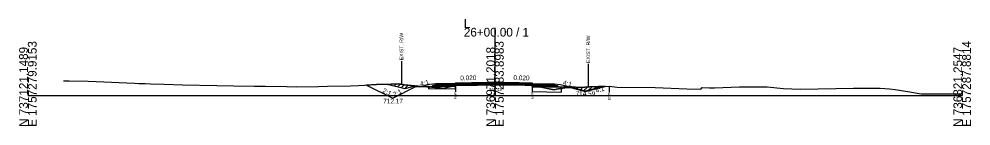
# Model space of a CAD drawing. Extents: x -26 to 4303, y -10 to 9577.
# Drawn here: x 997.2 to 1302.8, y 5990.3 to 6024.5 of the extents above; entities that cross this region are included whole.
import ezdxf

# ---------------------------------------------------------------- set-up
doc = ezdxf.new("R2010")
doc.units = 0
for name, color, linetype in [('Exist CMT Pavement', 7, 'Continuous'), ('Old_Level_10', 7, 'Continuous'), ('Old_Level_2', 7, 'Continuous'), ('Pattern 1', 7, 'Continuous'), ('Prop CMT Conc Surface', 7, 'Continuous'), ('Prop CMT Concrete Structures', 7, 'Continuous'), ('Prop CMT Concrete Wall', 7, 'Continuous'), ('Prop CMT Pvmt Course 1', 7, 'Continuous'), ('Prop CMT Pvmt Course 1 CG', 7, 'Continuous'), ('Prop CMT Pvmt Course 1 Wedge', 7, 'Continuous'), ('Prop CMT Pvmt Course 2', 7, 'Continuous'), ('Prop CMT Pvmt Course 2 Wedge', 7, 'Continuous'), ('Prop CMT Pvmt Course 3', 7, 'Continuous'), ('Prop CMT Pvmt Surface', 7, 'Continuous'), ('Prop CMT Pvmt Surface Shoulder', 7, 'Continuous'), ('Prop CMT Pvmt Wedge Surface 1', 7, 'Continuous'), ('Prop CMT Pvmt Wedge Surface 2', 7, 'Continuous'), ('Prop CMT Pvmt Wedge Surface 3', 7, 'Continuous'), ('Prop CMT Shld Paved Course 1', 7, 'Continuous'), ('Prop CMT Shld Paved Course 2', 7, 'Continuous'), ('Prop CMT Shld Paved Course 3', 7, 'Continuous'), ('Prop CMT Slope Grass', 7, 'Continuous'), ('Prop CMT Subgrade Earthwork', 7, 'Continuous'), ('Prop Road Sect_ Recs - UC Shallow (Outline)', 7, 'Continuous'), ('Prop Shade Light', 7, 'Continuous'), ('Prop XS DDE Elevations', 7, 'Continuous'), ('Prop XS Ditch Standard Text', 7, 'Continuous'), ('Prop XS Earthwork Shape', 7, 'Continuous'), ('Prop XS Hydro Elevations', 7, 'Continuous'), ('Prop XS SE Text', 7, 'Continuous'), ('Prop XS Side Slope Text', 7, 'Continuous'), ('Prop XS Wedging', 7, 'Continuous')]:
    doc.layers.add(name, color=color, linetype=linetype)

msp = doc.modelspace()

# ---------------------------------------------------------------- linework, layer by layer
at = {"layer": 'Exist CMT Pavement'}
for points in [[(1150, 6004.13), (1133, 6003.79)], [(1150, 6004.13), (1167, 6003.79)]]:
    msp.add_lwpolyline(points, dxfattribs=at)
at = {"layer": 'Old_Level_10'}
for p, q in [((1108.71, 6003.38), (1117.14, 5999.17)), ((1117.14, 5999.17), (1124.55, 6002.88)), ((1124.55, 6002.88), (1126.55, 6002.98))]:
    msp.add_line(p, q, dxfattribs=at)
at = {"layer": 'Old_Level_2'}
for p, q in [((1150, 6000), (1150, 6021.72)), ((1150, 6000), (1150, 6021.72)), ((1000, 6000), (1150, 6000)), ((1000, 6000), (1150, 6000)), ((1150, 6000), (1300, 6000)), ((1150, 6000), (1300, 6000))]:
    msp.add_line(p, q, dxfattribs=at)
at = {"layer": 'Pattern 1'}
for p, q in [((1116.46, 6003.35), (1116.74, 6003.63)), ((1117.59, 6003.07), (1118.22, 6003.7)), ((1118.72, 6002.79), (1119.61, 6003.68)), ((1119.85, 6002.51), (1120.85, 6003.5)), ((1120.98, 6002.22), (1122.14, 6003.38)), ((1122.86, 6002.68), (1123.44, 6003.26)), ((1161.92, 6003.05), (1162.18, 6003.32)), ((1163.06, 6002.78), (1163.34, 6003.06)), ((1164.45, 6002.75), (1164.5, 6002.81)), ((1173.84, 6002.57), (1174.01, 6002.74)), ((1175.05, 6002.37), (1175.44, 6002.75)), ((1176.18, 6002.08), (1176.75, 6002.66)), ((1177.31, 6001.8), (1178.18, 6002.67)), ((1178.44, 6001.52), (1179.68, 6002.76)), ((1179.96, 6001.62), (1181.17, 6002.83)), ((1181.84, 6002.09), (1182.63, 6002.88)), ((1183.73, 6002.56), (1184.1, 6002.93))]:
    msp.add_line(p, q, dxfattribs=at)
for points in [[(1124.71, 6003.15), (1121, 6002.22), (1115.39, 6003.62), (1116.62, 6003.63), (1119.13, 6003.75), (1120.8, 6003.51), (1124.62, 6003.15)], [(1161.92, 6002.8), (1164.77, 6002.75), (1161.92, 6003.38)], [(1179, 6001.38), (1185.38, 6002.97), (1183.25, 6002.9), (1180.75, 6002.81), (1179.73, 6002.76), (1177.26, 6002.62), (1174.51, 6002.82), (1173.64, 6002.69), (1172.95, 6002.58), (1174.28, 6002.56)]]:
    msp.add_lwpolyline(points, close=True, dxfattribs=at)
at = {"layer": 'Prop CMT Conc Surface'}
for points in [[(1137.34, 6003.63), (1133, 6003.54)], [(1137.34, 6003.42), (1137.34, 6003.63)], [(1161.92, 6003.43), (1161.92, 6003.64)], [(1161.92, 6003.64), (1167, 6003.54)], [(1133, 6003.54), (1133, 6003.33)], [(1133, 6003.33), (1137.34, 6003.42)], [(1167, 6003.33), (1161.92, 6003.43)], [(1167, 6003.54), (1167, 6003.33)]]:
    msp.add_lwpolyline(points, dxfattribs=at)
at = {"layer": 'Prop CMT Concrete Structures'}
for points in [[(1133, 6003.54), (1133, 6003.79)], [(1137.34, 6003.63), (1133, 6003.54)], [(1150, 6004), (1137.34, 6003.75)], [(1137.34, 6003.75), (1137.34, 6003.63)], [(1150, 6004), (1161.92, 6003.77)], [(1161.92, 6003.77), (1161.92, 6003.64)], [(1161.92, 6003.64), (1167, 6003.54)], [(1167, 6003.54), (1167, 6003.79)]]:
    msp.add_lwpolyline(points, dxfattribs=at)
at = {"layer": 'Prop CMT Pvmt Course 1'}
for points in [[(1137.34, 6003.42), (1133, 6003.33)], [(1133, 6003.33), (1133, 6003)], [(1133, 6003), (1137.34, 6003.08)], [(1137.34, 6003.08), (1137.34, 6003.42)], [(1161.92, 6003.43), (1167, 6003.33)], [(1161.92, 6003.1), (1161.92, 6003.43)], [(1167, 6003), (1161.92, 6003.1)], [(1167, 6003.33), (1167, 6003)]]:
    msp.add_lwpolyline(points, dxfattribs=at)
at = {"layer": 'Prop CMT Pvmt Course 1 Wedge'}
for points in [[(1137.34, 6004.07), (1137.75, 6004.08), (1137.83, 6004.08), (1138.14, 6004.09), (1139.33, 6004.11), (1139.59, 6004.11), (1139.95, 6004.12), (1140.06, 6004.12), (1142.45, 6004.17), (1142.5, 6004.17), (1144.41, 6004.21), (1144.94, 6004.22), (1144.95, 6004.22), (1147.37, 6004.27), (1147.45, 6004.27), (1147.48, 6004.27), (1148.16, 6004.29), (1148.53, 6004.29), (1149.98, 6004.32), (1150, 6004.32)], [(1137.34, 6003.25), (1137.34, 6004.07)], [(1150, 6004.32), (1150, 6003.49)], [(1150, 6004.32), (1151.04, 6004.3), (1151.29, 6004.3), (1151.68, 6004.29), (1152.37, 6004.28), (1152.45, 6004.27), (1154.68, 6004.23), (1154.95, 6004.22), (1157.12, 6004.18), (1157.45, 6004.17), (1157.81, 6004.17), (1159.96, 6004.12), (1160.88, 6004.11), (1161.13, 6004.1), (1161.23, 6004.1), (1161.44, 6004.09), (1161.46, 6004.09), (1161.92, 6004.08)], [(1161.92, 6004.08), (1161.92, 6003.38)], [(1150, 6003.49), (1149.98, 6003.49), (1148.53, 6003.47), (1148.16, 6003.44), (1147.48, 6003.46), (1147.45, 6003.46), (1147.37, 6003.46), (1144.95, 6003.42), (1144.94, 6003.42), (1144.41, 6003.41), (1142.5, 6003.39), (1142.45, 6003.39), (1140.06, 6003.38), (1139.95, 6003.38), (1139.59, 6003.36), (1139.33, 6003.37), (1138.14, 6003.34), (1137.83, 6003.34), (1137.75, 6003.34), (1137.34, 6003.25)], [(1161.92, 6003.38), (1161.46, 6003.4), (1161.44, 6003.4), (1161.23, 6003.4), (1161.13, 6003.4), (1160.88, 6003.41), (1159.96, 6003.41), (1157.81, 6003.43), (1157.45, 6003.43), (1157.12, 6003.44), (1154.95, 6003.47), (1154.68, 6003.47), (1152.45, 6003.46), (1152.37, 6003.46), (1151.68, 6003.47), (1151.29, 6003.48), (1151.04, 6003.47), (1150, 6003.49)]]:
    msp.add_lwpolyline(points, dxfattribs=at)
at = {"layer": 'Prop CMT Pvmt Course 2'}
for points in [[(1133, 6003.79), (1131, 6003.75), (1130.74, 6003.49)], [(1133, 6003.54), (1133, 6003.79)], [(1167, 6003.79), (1169, 6003.75), (1169.26, 6003.49)], [(1167, 6003.54), (1167, 6003.79)], [(1130.74, 6003.49), (1133, 6003.54)], [(1169.26, 6003.49), (1167, 6003.54)]]:
    msp.add_lwpolyline(points, dxfattribs=at)
at = {"layer": 'Prop CMT Pvmt Course 2 Wedge'}
for points in [[(1131, 6003.75), (1129, 6003.59), (1126.55, 6002.98)], [(1169, 6003.75), (1171, 6003.59), (1179, 6001.59), (1184.4, 6002.94)]]:
    msp.add_lwpolyline(points, dxfattribs=at)
at = {"layer": 'Prop CMT Pvmt Course 3'}
for points in [[(1133, 6003.54), (1130.74, 6003.49), (1130.53, 6003.28)], [(1130.53, 6003.28), (1133, 6003.33)], [(1133, 6003.33), (1133, 6003.54)], [(1167, 6003.54), (1169.26, 6003.49), (1169.47, 6003.28)], [(1167, 6003.33), (1167, 6003.54)], [(1169.47, 6003.28), (1167, 6003.33)]]:
    msp.add_lwpolyline(points, dxfattribs=at)
at = {"layer": 'Prop CMT Pvmt Surface'}
for points in [[(1150, 6003.88), (1133, 6003.54)], [(1133, 6003.54), (1133, 6003.79)], [(1150, 6003.88), (1167, 6003.54)], [(1167, 6003.54), (1167, 6003.79)]]:
    msp.add_lwpolyline(points, dxfattribs=at)
at = {"layer": 'Prop CMT Pvmt Surface Shoulder'}
for points in [[(1137.34, 6003.25), (1137.75, 6003.34), (1137.83, 6003.34), (1138.14, 6003.34), (1139.33, 6003.37), (1139.59, 6003.36), (1139.95, 6003.38), (1140.06, 6003.38), (1142.45, 6003.39), (1142.5, 6003.39), (1144.41, 6003.41), (1144.94, 6003.42), (1144.95, 6003.42), (1147.37, 6003.46), (1147.45, 6003.46), (1147.48, 6003.46), (1148.16, 6003.44), (1148.53, 6003.47), (1149.98, 6003.49), (1150, 6003.49)], [(1150, 6003.49), (1151.04, 6003.47), (1151.29, 6003.48), (1151.68, 6003.47), (1152.37, 6003.46), (1152.45, 6003.46), (1154.68, 6003.47), (1154.95, 6003.47), (1157.12, 6003.44), (1157.45, 6003.43), (1157.81, 6003.43), (1159.96, 6003.41), (1160.88, 6003.41), (1161.13, 6003.4), (1161.23, 6003.4), (1161.44, 6003.4), (1161.46, 6003.4), (1161.92, 6003.38)]]:
    msp.add_lwpolyline(points, dxfattribs=at)
at = {"layer": 'Prop CMT Pvmt Wedge Surface 1'}
for p, q in [((1126.55, 6002.98), (1129.02, 6002.79)), ((1133.02, 6002.87), (1129.02, 6002.79)), ((1137.34, 6002.96), (1133.02, 6002.87)), ((1161.92, 6002.97), (1166.98, 6002.87)), ((1166.98, 6002.87), (1174.47, 6002.72))]:
    msp.add_line(p, q, dxfattribs=at)
for points in [[(1137.34, 6003.25), (1137.34, 6002.96)], [(1161.92, 6003.38), (1161.92, 6002.97)]]:
    msp.add_lwpolyline(points, dxfattribs=at)
at = {"layer": 'Prop CMT Pvmt Wedge Surface 2'}
for points in [[(1137.34, 6003.75), (1137.75, 6003.76), (1137.83, 6003.76), (1138.14, 6003.77), (1139.33, 6003.79), (1139.59, 6003.8), (1139.95, 6003.8), (1140.06, 6003.8), (1142.45, 6003.85), (1142.5, 6003.85), (1144.41, 6003.89), (1144.94, 6003.9), (1144.95, 6003.9), (1147.37, 6003.95), (1147.45, 6003.95), (1147.48, 6003.95), (1148.16, 6003.97), (1148.53, 6003.97), (1149.98, 6004), (1150, 6004)], [(1150, 6003.88), (1149.98, 6003.88), (1148.53, 6003.85), (1148.16, 6003.84), (1147.48, 6003.83), (1147.45, 6003.83), (1147.37, 6003.83), (1144.95, 6003.78), (1144.94, 6003.78), (1144.41, 6003.77), (1142.5, 6003.73), (1142.45, 6003.73), (1140.06, 6003.68), (1139.95, 6003.68), (1139.59, 6003.67), (1139.33, 6003.67), (1138.14, 6003.64), (1137.83, 6003.63), (1137.75, 6003.63), (1137.34, 6003.63)], [(1137.34, 6002.6), (1137.34, 6003.75)], [(1150, 6004), (1150, 6003.88)], [(1150, 6004), (1151.04, 6003.98), (1151.29, 6003.98), (1151.68, 6003.97), (1152.37, 6003.96), (1152.45, 6003.95), (1154.68, 6003.91), (1154.95, 6003.9), (1157.12, 6003.86), (1157.45, 6003.85), (1157.81, 6003.85), (1159.96, 6003.8), (1160.88, 6003.79), (1161.13, 6003.78), (1161.23, 6003.78), (1161.44, 6003.77), (1161.46, 6003.77), (1161.92, 6003.77)], [(1161.92, 6003.64), (1161.46, 6003.65), (1161.44, 6003.65), (1161.23, 6003.65), (1161.13, 6003.66), (1160.88, 6003.66), (1159.96, 6003.68), (1157.81, 6003.72), (1157.45, 6003.73), (1157.12, 6003.74), (1154.95, 6003.78), (1154.68, 6003.78), (1152.45, 6003.83), (1152.37, 6003.83), (1151.68, 6003.84), (1151.29, 6003.85), (1151.04, 6003.86), (1150, 6003.88)], [(1161.92, 6003.77), (1161.92, 6002.73)]]:
    msp.add_lwpolyline(points, dxfattribs=at)
at = {"layer": 'Prop CMT Pvmt Wedge Surface 3'}
for points in [[(1137.34, 6003.63), (1137.75, 6003.63), (1137.83, 6003.63), (1138.14, 6003.64), (1139.33, 6003.67), (1139.59, 6003.67), (1139.95, 6003.68), (1140.06, 6003.68), (1142.45, 6003.73), (1142.5, 6003.73), (1144.41, 6003.77), (1144.94, 6003.78), (1144.95, 6003.78), (1147.37, 6003.83), (1147.45, 6003.83), (1147.48, 6003.83), (1148.16, 6003.84), (1148.53, 6003.85), (1149.98, 6003.88), (1150, 6003.88)], [(1150, 6003.67), (1149.98, 6003.67), (1148.53, 6003.64), (1148.16, 6003.63), (1147.48, 6003.62), (1147.45, 6003.62), (1147.37, 6003.62), (1144.95, 6003.57), (1144.94, 6003.57), (1144.41, 6003.56), (1142.5, 6003.52), (1142.45, 6003.52), (1140.06, 6003.47), (1139.95, 6003.47), (1139.59, 6003.46), (1139.33, 6003.46), (1138.14, 6003.43), (1137.83, 6003.43), (1137.75, 6003.43), (1137.34, 6003.42)], [(1137.34, 6003.42), (1137.34, 6003.63)], [(1150, 6003.88), (1150, 6003.67)], [(1150, 6003.88), (1151.04, 6003.86), (1151.29, 6003.85), (1151.68, 6003.84), (1152.37, 6003.83), (1152.45, 6003.83), (1154.68, 6003.78), (1154.95, 6003.78), (1157.12, 6003.74), (1157.45, 6003.73), (1157.81, 6003.72), (1159.96, 6003.68), (1160.88, 6003.66), (1161.13, 6003.66), (1161.23, 6003.65), (1161.44, 6003.65), (1161.46, 6003.65), (1161.92, 6003.64)], [(1161.92, 6003.43), (1161.46, 6003.44), (1161.44, 6003.44), (1161.23, 6003.45), (1161.13, 6003.45), (1160.88, 6003.45), (1159.96, 6003.47), (1157.81, 6003.51), (1157.45, 6003.52), (1157.12, 6003.53), (1154.95, 6003.57), (1154.68, 6003.58), (1152.45, 6003.62), (1152.37, 6003.62), (1151.68, 6003.64), (1151.29, 6003.64), (1151.04, 6003.65), (1150, 6003.67)], [(1161.92, 6003.64), (1161.92, 6003.43)]]:
    msp.add_lwpolyline(points, dxfattribs=at)
at = {"layer": 'Prop CMT Shld Paved Course 1'}
for points in [[(1133, 6003.33), (1133, 6003.79)], [(1150, 6003.67), (1133, 6003.33)], [(1150, 6003.67), (1167, 6003.33)], [(1167, 6003.33), (1167, 6003.79)]]:
    msp.add_lwpolyline(points, dxfattribs=at)
at = {"layer": 'Prop CMT Shld Paved Course 2'}
for points in [[(1133, 6003.79), (1131, 6003.75)], [(1167, 6003.79), (1169, 6003.75)]]:
    msp.add_lwpolyline(points, dxfattribs=at)
at = {"layer": 'Prop CMT Shld Paved Course 3'}
for points in [[(1150, 6004.13), (1133, 6003.79)], [(1133, 6003.79), (1133, 6003.54)], [(1133, 6003.54), (1137.34, 6003.63)], [(1137.34, 6003.75), (1150, 6004)], [(1137.34, 6003.63), (1137.34, 6003.75)], [(1150, 6004.13), (1167, 6003.79)], [(1161.92, 6003.77), (1150, 6004)], [(1161.92, 6003.64), (1161.92, 6003.77)], [(1167, 6003.54), (1161.92, 6003.64)], [(1167, 6003.79), (1167, 6003.54)]]:
    msp.add_lwpolyline(points, dxfattribs=at)
at = {"layer": 'Prop CMT Slope Grass'}
msp.add_lwpolyline([(1011.44, 6004.78), (1013.24, 6004.79), (1019.34, 6004.62), (1021.91, 6004.5), (1034.2, 6003.99), (1035.62, 6003.94), (1037.7, 6003.87), (1039.33, 6003.79), (1043.72, 6003.72), (1049.61, 6003.46), (1060.7, 6003.3), (1066.18, 6003.14), (1072.72, 6002.99), (1076.19, 6003), (1083, 6002.9), (1086.19, 6002.84), (1093.28, 6002.96), (1096.2, 6002.99), (1103.55, 6003.16), (1106.2, 6003.22), (1111.98, 6003.6), (1116.61, 6003.63), (1119.13, 6003.75), (1120.81, 6003.5), (1129.76, 6002.68), (1133.36, 6002.32), (1135.78, 6002.89), (1137.75, 6003.34), (1138.14, 6003.34), (1139.59, 6003.36), (1140.06, 6003.38), (1142.5, 6003.39), (1144.42, 6003.41), (1144.95, 6003.42), (1147.48, 6003.46), (1148.16, 6003.44), (1148.53, 6003.47), (1149.98, 6003.49), (1151.29, 6003.48), (1151.68, 6003.47), (1152.45, 6003.46), (1154.95, 6003.47), (1157.12, 6003.44), (1157.45, 6003.43), (1159.55, 6003.41), (1159.96, 6003.41), (1161.44, 6003.4), (1161.93, 6003.38), (1167.35, 6002.17), (1169.01, 6001.91), (1169.75, 6002.1), (1174.52, 6002.82), (1177.26, 6002.62), (1180.47, 6002.8), (1186.67, 6003.02), (1189.19, 6002.77), (1201.41, 6002.64), (1211.57, 6002.17), (1216.1, 6002.06), (1216.51, 6002.56), (1218.83, 6002.54), (1220.51, 6002.53), (1228.46, 6002.78), (1237.39, 6002.79), (1242.6, 6002.3), (1247.95, 6002.13), (1265.09, 6002.37), (1266.94, 6002.39), (1273.68, 6002.38), (1276.71, 6002.2), (1278.47, 6002.02), (1283.16, 6001.21), (1284.88, 6000.92), (1286.89, 6000.6), (1300, 6000.6)], dxfattribs=at)
at = {"layer": 'Prop CMT Subgrade Earthwork'}
for points in [[(1133, 6003.33), (1130.53, 6003.28), (1130.03, 6003.27), (1129.69, 6002.93)], [(1129.69, 6002.93), (1133, 6003)], [(1133, 6003), (1133, 6003.33)], [(1167, 6003.33), (1169.47, 6003.28), (1169.97, 6003.27), (1170.31, 6002.93)], [(1167, 6003), (1167, 6003.33)], [(1170.31, 6002.93), (1167, 6003)]]:
    msp.add_lwpolyline(points, dxfattribs=at)
at = {"layer": 'Prop Road Sect_ Recs - UC Shallow (Outline)'}
for p, q in [((1128.7, 6002.22), (1137.35, 6002.25)), ((1137.35, 6002.25), (1137.34, 6003.25))]:
    msp.add_line(p, q, dxfattribs=at)
msp.add_lwpolyline([(1128.7, 6002.22), (1128.7, 6002.79), (1129.76, 6002.68), (1133.36, 6002.32), (1135.78, 6002.89), (1137.34, 6003.25)], dxfattribs=at)
msp.add_lwpolyline([(1161.91, 6001.3), (1171.37, 6001.12), (1171.39, 6002.35), (1170.58, 6002.22), (1169.76, 6002.1), (1169.01, 6001.91), (1167.34, 6002.17), (1165.82, 6002.51), (1164.77, 6002.75), (1161.92, 6002.8)], close=True, dxfattribs=at)
at = {"layer": 'Prop Shade Light'}
for p, q in [((1128.7, 6002.78), (1128.7, 6002.22)), ((1128.7, 6002.22), (1137.35, 6002.25)), ((1137.34, 6003.25), (1135.78, 6002.89)), ((1137.35, 6002.25), (1137.34, 6003.25)), ((1161.93, 6002.63), (1161.92, 6001.3)), ((1161.92, 6001.3), (1171.37, 6001.12)), ((1169.01, 6001.91), (1167.23, 6002.2)), ((1169.76, 6002.1), (1169.01, 6001.91)), ((1171.39, 6002.35), (1169.76, 6002.1)), ((1171.37, 6001.12), (1171.39, 6002.35))]:
    msp.add_line(p, q, dxfattribs=at)
for points in [[(1135.78, 6002.89), (1133.36, 6002.32), (1129.76, 6002.68), (1128.7, 6002.78)], [(1163.87, 6002.77), (1162.78, 6002.79), (1161.92, 6002.8), (1161.93, 6002.63)], [(1167.23, 6002.2), (1164.77, 6002.75), (1163.87, 6002.77)]]:
    msp.add_lwpolyline(points, dxfattribs=at)
at = {"layer": 'Prop XS DDE Elevations'}
for points in [[(1135.94, 6002.93), (1133.02, 6002.87), (1129.02, 6002.79), (1126.55, 6002.98), (1129.76, 6002.68), (1133.36, 6002.32), (1135.78, 6002.89)], [(1135.94, 6002.93), (1137.34, 6003.25), (1137.34, 6002.96)], [(1137.75, 6003.34), (1137.83, 6003.34), (1138.14, 6003.34)], [(1138.14, 6003.34), (1139.33, 6003.37), (1139.59, 6003.36)], [(1139.59, 6003.36), (1139.95, 6003.38), (1140.06, 6003.38)], [(1144.41, 6003.41), (1144.95, 6003.42), (1144.94, 6003.42)], [(1144.95, 6003.42), (1147.37, 6003.46), (1147.44, 6003.46)], [(1149.98, 6003.49), (1151.29, 6003.48), (1151.04, 6003.47), (1150, 6003.49)], [(1151.68, 6003.47), (1152.45, 6003.46), (1152.37, 6003.46)], [(1152.45, 6003.46), (1154.95, 6003.47), (1154.68, 6003.47)], [(1161.23, 6003.4), (1161.44, 6003.4), (1159.96, 6003.41), (1160.88, 6003.41), (1161.13, 6003.4)], [(1161.44, 6003.4), (1161.46, 6003.4), (1161.92, 6003.38)], [(1161.93, 6003.38), (1163.93, 6002.93), (1161.92, 6002.97), (1161.92, 6003.38)], [(1169.75, 6002.1), (1173.94, 6002.73), (1166.98, 6002.87), (1163.93, 6002.93), (1167.35, 6002.17), (1169.01, 6001.91)], [(1173.94, 6002.73), (1174.24, 6002.78), (1174.47, 6002.72)], [(1179, 6001.59), (1184.4, 6002.94), (1180.47, 6002.8), (1177.26, 6002.62), (1174.52, 6002.82), (1174.24, 6002.78), (1174.47, 6002.72)]]:
    msp.add_lwpolyline(points, close=True, dxfattribs=at)
at = {"layer": 'Prop XS Ditch Standard Text'}
for p, q in [((1119.94, 6011.03), (1119.94, 6003.63)), ((1179.94, 6010.17), (1179.94, 6002.77)), ((1137.34, 6003.25), (1137.34, 6001.2)), ((1161.92, 6003.38), (1161.92, 6001.33)), ((1186.67, 6003.02), (1186.67, 6000.97))]:
    msp.add_line(p, q, dxfattribs=at)
at = {"layer": 'Prop XS Earthwork Shape'}
msp.add_lwpolyline([(1117.14, 5999.17), (1124.55, 6002.88), (1126.55, 6002.98), (1120.81, 6003.5), (1119.13, 6003.75), (1116.61, 6003.63), (1111.98, 6003.6), (1108.71, 6003.38)], close=True, dxfattribs=at)
at = {"layer": 'Prop XS Wedging'}
for p, q in [((1150, 6004), (1137.34, 6003.75)), ((1137.34, 6003.63), (1150, 6003.88)), ((1137.34, 6003.63), (1150, 6003.88)), ((1137.34, 6003.75), (1137.34, 6003.63)), ((1137.34, 6003.63), (1137.34, 6003.42)), ((1161.92, 6003.77), (1150, 6004)), ((1161.91, 6003.64), (1150, 6003.88)), ((1150, 6003.88), (1161.92, 6003.64)), ((1150, 6003.88), (1150, 6003.88)), ((1161.92, 6003.64), (1161.92, 6003.77)), ((1161.92, 6003.43), (1161.92, 6003.64)), ((1137.34, 6003.42), (1137.34, 6003.25)), ((1161.92, 6003.38), (1161.92, 6003.43))]:
    msp.add_line(p, q, dxfattribs=at)
for points in [[(1150, 6003.88), (1150, 6003.88), (1137.34, 6003.63)], [(1161.92, 6003.64), (1150, 6003.88), (1150, 6003.88)], [(1137.34, 6003.25), (1137.75, 6003.34), (1138.14, 6003.34), (1139.59, 6003.36), (1140.06, 6003.38), (1142.5, 6003.39), (1144.42, 6003.41), (1144.95, 6003.42), (1147.48, 6003.46), (1148.16, 6003.44), (1148.53, 6003.47), (1149.98, 6003.49), (1151.29, 6003.48), (1151.68, 6003.47), (1152.45, 6003.46), (1154.95, 6003.47), (1157.12, 6003.44), (1157.45, 6003.43), (1159.55, 6003.41), (1159.96, 6003.41), (1161.44, 6003.4), (1161.92, 6003.38)], [(1161.92, 6003.38), (1161.92, 6003.38), (1161.92, 6003.38)]]:
    msp.add_lwpolyline(points, dxfattribs=at)

# ---------------------------------------------------------------- texts
at = {"layer": 'Old_Level_2'}
for s, p in [('L', (1140, 6021.72)), ('L', (1140, 6021.72)), ('26+00.00 / 1', (1140, 6018.92)), ('26+00.00 / 1', (1140, 6018.92))]:
    msp.add_text(s, height=2.8, dxfattribs=at).set_placement(p)
for s, p in [('E 1757279.9153', (1002.8, 5990)), ('E 1757279.9153', (1002.8, 5990)), ('E 1757283.8983', (1152.8, 5990)), ('E 1757283.8983', (1152.8, 5990)), ('E 1757287.8814', (1302.8, 5990)), ('E 1757287.8814', (1302.8, 5990)), ('N 737121.1489', (1000, 5990)), ('N 737121.1489', (1000, 5990)), ('N 736971.2018', (1150, 5990)), ('N 736971.2018', (1150, 5990)), ('N 736821.2547', (1300, 5990)), ('N 736821.2547', (1300, 5990))]:
    msp.add_text(s, height=2.8, rotation=90, dxfattribs=at).set_placement(p)
at = {"layer": 'Prop CMT Concrete Wall'}
for rotation, p in [(334.1383, (1113.73, 6001.14)), (25.8617, (1117.63, 5999.61))]:
    msp.add_text('2:1', height=1.5, rotation=rotation, dxfattribs=at).set_placement(p)
msp.add_text('712.17', height=1.5, dxfattribs=at).set_placement((1114.11, 5997.53))
at = {"layer": 'Prop CMT Pvmt Course 1 CG'}
msp.add_text('716.49', height=1, dxfattribs=at).set_placement((1147.99, 6001.49))
at = {"layer": 'Prop XS Ditch Standard Text'}
for s, height, p in [('EXIST. R/W', 1.181, (1120.53, 6011.33)), ('EXIST. R/W', 1.181, (1180.53, 6010.48)), ('EOP', 0.787, (1137.74, 5998.8)), ('EOP', 0.787, (1162.31, 5998.93)), ('EOP', 0.787, (1187.06, 5998.57))]:
    msp.add_text(s, height=height, rotation=90, dxfattribs=at).set_placement(p)
at = {"layer": 'Prop XS Hydro Elevations'}
msp.add_text('714.59', height=1.5, dxfattribs=at).set_placement((1175.88, 5999.89))
at = {"layer": 'Prop XS SE Text'}
for rotation, p in [(1.1458, (1138.86, 6004.91)), (358.8542, (1155.9, 6005.01))]:
    msp.add_text('0.020', height=1.5, rotation=rotation, dxfattribs=at).set_placement(p)
at = {"layer": 'Prop XS Side Slope Text'}
for rotation, p in [(14.0362, (1126.13, 6003.02)), (345.9638, (1171.7, 6003.53)), (14.0362, (1182.46, 6000.89))]:
    msp.add_text('4:1', height=1.5, rotation=rotation, dxfattribs=at).set_placement(p)

doc.saveas('drawing.dxf')
